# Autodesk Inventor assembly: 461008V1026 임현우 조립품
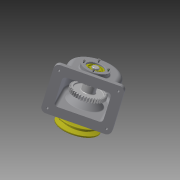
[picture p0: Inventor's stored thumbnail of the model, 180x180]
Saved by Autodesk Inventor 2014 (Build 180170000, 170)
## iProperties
Created: 2016-10
Part Number: 461008V1026 임현우 조립품
Document SubType Name: Assembly
Designer: 703-18
Author: 703-18
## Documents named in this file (15)
- C:\Users\703-18\Desktop\461008V1026 임현우 조립품.iam
- C:\Users\703-18\Desktop\461008V1026 임현우.ipt
- C:\Users\703-18\Desktop\461008V1026\V-벨트풀리.ipt
- C:\Users\703-18\Desktop\461008V1026\뒤커버.ipt
- C:\Users\703-18\Desktop\461008V1026\멈춤나사 - M4x10.ipt
- C:\Users\703-18\Desktop\461008V1026\베어링 6203.ipt
- C:\Users\703-18\Desktop\461008V1026\볼트 M3 x 8.ipt
- C:\Users\703-18\Desktop\461008V1026\볼트 M3 x 10.ipt
- C:\Users\703-18\Desktop\461008V1026\부시.ipt
- C:\Users\703-18\Desktop\461008V1026\스퍼기어.ipt
- C:\Users\703-18\Desktop\461008V1026\앞커버.ipt
- C:\Users\703-18\Desktop\461008V1026\오일씰 28 40 8.ipt
- C:\Users\703-18\Desktop\461008V1026\축.ipt
- C:\Users\703-18\Desktop\461008V1026\키 - 5 x 5 x 18.ipt
- C:\Users\703-18\Desktop\461008V1026\키 - 6 x 6 x 22.ipt
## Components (10 placed, 4 different names)
1. 461008V1026 임현우:1
2. V-벨트풀리:1
3. ISO 4762 M3 x 8:1
4. ISO 4762 M3 x 8:2
5. ISO 4762 M3 x 8:3
6. ISO 4762 M3 x 8:4
7. ISO 4762 M3 x 10:1
8. ISO 4762 M3 x 10:2
9. ISO 4762 M3 x 10:3
10. ISO 4762 M3 x 10:4
